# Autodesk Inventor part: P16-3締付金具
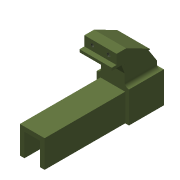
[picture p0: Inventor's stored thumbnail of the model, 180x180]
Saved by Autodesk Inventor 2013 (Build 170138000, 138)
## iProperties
Created: 2008-07
Part Number: P16-3締付金具
Document SubType Name: Modeling
Designer: y-shimohigashi
Density: 1 g/cm^3
Material: 一般
Author: y-shimohigashi
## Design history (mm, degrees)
sketch "スケッチ3"
  geometry: L1 (43, 22)-(43, 80); L2 (43, 80)-(38, 80); L3 (38, 80)-(38, 93); L4 (38, 93)-(16, 127); L5 (16, 127)-(-27, 149); L6 (-27, 149)-(-45, 149); L7 (-45, 149)-(-45, 131); L8 (-45, 131)-(-54, 131); L9 (-54, 131)-(-54, 126); L10 (-54, 126)-(-44, 126); L11 (-44, 126)-(-31, 126); L12 (-31, 126)-(-22, 102); L13 (-22, 102)-(-22, 22); L14 (-22, 22)-(43, 22); 1 further point
  constraints: 28 end point, 6 parallel, 1 horizontal, 1 perpendicular, 1 vertical
  dimensions: "d4" = 58 distance of L1.start L1.end; "d5" = 13 distance of L2.end L3.end; "d6" = 34 vertical distance of L3.end L4.end; "d7" = 22 vertical distance of L4.end L5.end; "d8" = 5 distance of L1.end L2.end; "d9" = 22 horizontal distance of L3.end L4.end; "d10" = 43 horizontal distance of L4.end L5.end; "d11" = 18 distance of L5.end L6.end; "d12" = 9 distance of L7.end L8.end; "d13" = 18 distance of L6.end L7.end; "d14" = 5 distance of L8.end L9.end; "d15" = 10 distance of L9.end L10.end; "d16" = 24 vertical distance of L11.end L12.end; "d17" = 80 distance of L12.end L13.end; "d18" = 65 distance between parallel lines of L1 L13; "d19" = 13 distance of L10.end L11.end; "d66" = 43 distance from line of L1 point (0, 0); "d67" = 22 distance from line of point (0, 0) L14
extrude "押し出し2" new body sketch "スケッチ3" stored distance "d20" = 60; taper "d21" = 0 deg
sketch "スケッチ4"
  geometry: L1 (0, 0)-(60, 0) reference; L2 (60, 0)-(52, 0); L3 (52, 0)-(52, -45); L4 (52, -45)-(60, -45); L5 (60, -45)-(60, 0); L6 (0, 0)-(8, 0); L7 (8, 0)-(8, -45); L8 (8, -45)-(0, -45); L9 (0, -45)-(0, 0)
  constraints: 16 end point, 4 parallel, 2 collinear, 2 horizontal, 2 perpendicular
  dimensions: "d22" = 8 distance of L3.end L4.end; "d23" = 45 distance of L4.end L1.end
extrude "押し出し3" cut sketch "スケッチ4" stored distance "d24" = 60; taper "d25" = 0 deg
sketch "スケッチ9"
  geometry: L1 (-60, 58)-(-60, 0) reference; L2 (-60, 0)-(0, 0) reference; L3 (0, 0)-(0, 58) reference; L4 (0, 58)-(-60, 58) reference; L5 (-53, 51)-(-53, 0); L6 (-7, 0)-(-7, 51); L7 (-7, 51)-(-53, 51); L8 (-53, 0)-(-44.5, 0); L9 (-44.5, 42.5)-(-15.5, 42.5); L10 (-15.5, 42.5)-(-15.5, 0); L11 (-44.5, 42.5)-(-44.5, 0); L12 (-15.5, 0)-(-7, 0)
  constraints: 16 end point, 4 point on line, 2 parallel, 2 perpendicular, 1 collinear
  dimensions: "d68" = 7 distance between parallel lines of L7 L4; "d69" = 7 distance between parallel lines of L5 L1 (= d68); "d70" = 7 distance between parallel lines of L3 L6 (= d68); "d71" = 8.5 distance between parallel lines of L9 L7; "d72" = 8.5 distance between parallel lines of L11 L5 (= d71)
extrude "押し出し6" join sketch "スケッチ9" distance "d74" = 215; taper "d75" = 0 deg
sketch "スケッチ10"
  geometry: L1 (60, 0)-(0, 0) reference; 2 further points
  constraints: 1 midpoint, 1 vertical alignment
  dimensions: "d85" = 25.5 distance from line of L1 point (30, -25.5)
hole "穴4" sketch "スケッチ10" at (30, -25.5) diameter "d76" = 16; stored, may be unused: countersink angle "d80" = 90 deg, drill point angle "d82" = 118 deg; dims "d77" = 6, "d78" = 36, "d79" = 15, "d81" = 8
feature "ねじ1" dims "d83" = 10, "d84" = 0
sketch "スケッチ11"
  geometry: L1 (30, -152.4)-(30, 25.4) reference; L2 (60, -18)-(60, 0) reference; 3 further points
  constraints: 2 horizontal alignment, 1 midpoint, 1 symmetric about line
  dimensions: "d88" = 30 distance of point (45, -9) point (15, -9)
hole "穴5" sketch "スケッチ11" at (15, -9), (45, -9) diameter "d89" = 6.647; stored, may be unused: countersink angle "d93" = 90 deg, drill point angle "d95" = 118 deg; dims "d90" = 6, "d91" = 36, "d92" = 15, "d94" = 8
fillet "フィレット4" dims "d96" = 8
node "ソリッド1"
node "ソリッド ボディ"
node "サーフェス ボディ"
node "投影ループ2"
